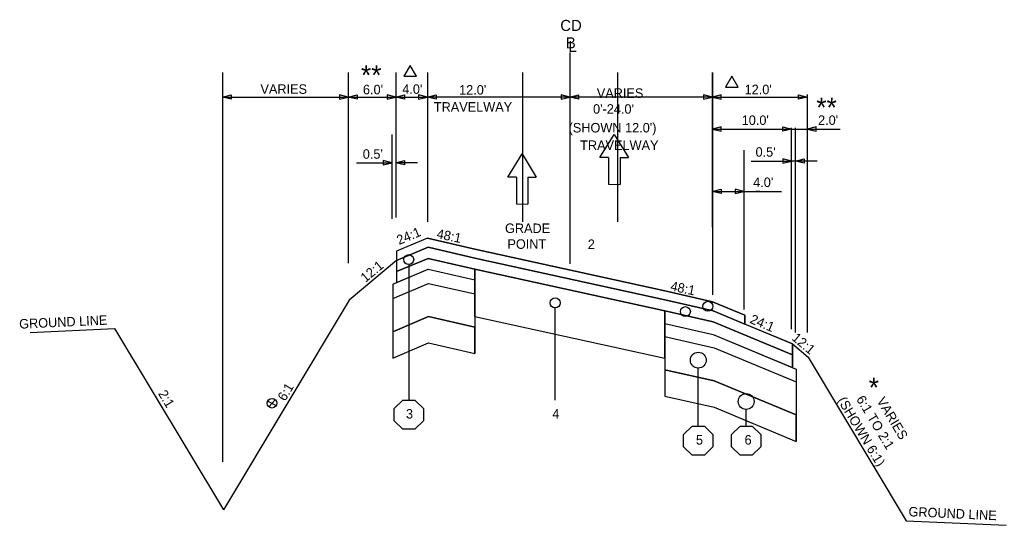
# Model space of a CAD drawing. Extents: x 5017 to 5774, y 4942 to 5266.
# Drawn here: x 5649.7 to 5774.4, y 4995.3 to 5059.2 of the extents above; entities that cross this region are included whole.
import ezdxf

# ---------------------------------------------------------------- set-up
doc = ezdxf.new("R2010")
doc.units = 0
for name, color, linetype in [('Level 20', 7, 'Continuous'), ('Level 25', 7, 'Continuous'), ('RD_QTY_Intermediate', 7, 'Continuous'), ('RD_QTY_Surf_Course', 7, 'Continuous'), ('RD_SHT_Typical', 7, 'Continuous'), ('RD_TX_TypSect', 7, 'Continuous'), ('RD_XS_ExGround', 7, 'Continuous'), ('RD_XS_ExPaveRet', 7, 'Continuous'), ('typical_on', 7, 'Continuous')]:
    doc.layers.add(name, color=color, linetype=linetype)

msp = doc.modelspace()

# ---------------------------------------------------------------- linework, layer by layer
at = {"layer": 'Level 20'}
for p, q in [((5723.05, 5041.76), (5724.87, 5044.67)), ((5724.87, 5044.67), (5726.65, 5041.75)), ((5711.4, 5039.28), (5713.23, 5042.2)), ((5713.23, 5042.2), (5715.01, 5039.27)), ((5724.14, 5041.76), (5723.05, 5041.76)), ((5724.14, 5041.76), (5724.14, 5038.36)), ((5725.6, 5041.75), (5726.65, 5041.75)), ((5725.6, 5041.75), (5725.6, 5038.35)), ((5712.5, 5039.28), (5711.4, 5039.28)), ((5712.5, 5039.28), (5712.5, 5035.88)), ((5713.95, 5039.27), (5715.01, 5039.27)), ((5713.95, 5039.27), (5713.95, 5035.87)), ((5724.14, 5038.36), (5725.6, 5038.35)), ((5712.5, 5035.88), (5713.95, 5035.87))]:
    msp.add_line(p, q, dxfattribs=at)
at = {"layer": 'RD_QTY_Intermediate'}
for p, q in [((5701.37, 5029), (5697.37, 5027.34)), ((5707.26, 5027.65), (5701.37, 5029)), ((5697.37, 5025.96), (5701.34, 5027.64)), ((5701.34, 5027.64), (5707.26, 5026.28)), ((5707.26, 5026.28), (5707.26, 5027.65)), ((5697.37, 5027.34), (5697.37, 5025.96)), ((5737.37, 5020.97), (5731.26, 5022.37)), ((5731.26, 5022.37), (5731.26, 5020.78)), ((5731.26, 5020.78), (5737.37, 5019.37)), ((5747.37, 5016.8), (5737.37, 5020.97)), ((5737.37, 5019.37), (5747.37, 5015.21)), ((5747.37, 5015.21), (5747.37, 5016.8))]:
    msp.add_line(p, q, dxfattribs=at)
at = {"layer": 'RD_QTY_Surf_Course'}
for p, q in [((5701.26, 5031.56), (5697.37, 5029.93)), ((5707.26, 5030.18), (5701.26, 5031.56)), ((5697.37, 5028.73), (5701.37, 5030.4)), ((5701.37, 5030.4), (5697.37, 5028.73)), ((5701.37, 5030.4), (5707.26, 5029.05)), ((5707.26, 5029.05), (5701.37, 5030.4)), ((5731.26, 5024.9), (5707.26, 5030.18)), ((5697.37, 5029.93), (5697.37, 5028.73)), ((5697.37, 5027.34), (5701.37, 5029)), ((5701.37, 5029), (5707.26, 5027.65)), ((5707.26, 5029.05), (5731.26, 5023.77)), ((5731.26, 5023.77), (5707.26, 5029.05)), ((5697.37, 5028.73), (5697.37, 5027.34)), ((5707.26, 5027.65), (5731.26, 5022.37)), ((5737.26, 5023.52), (5731.26, 5024.9)), ((5731.26, 5023.77), (5737.37, 5022.37)), ((5737.37, 5022.37), (5731.26, 5023.77)), ((5741.37, 5021.81), (5737.26, 5023.52)), ((5701.4, 5021.65), (5696.88, 5019.73)), ((5707.26, 5020.33), (5701.4, 5021.65)), ((5731.26, 5022.37), (5737.37, 5020.97)), ((5737.37, 5022.37), (5741.37, 5020.7)), ((5741.37, 5020.7), (5737.37, 5022.37)), ((5741.37, 5020.7), (5741.37, 5021.81)), ((5707.26, 5017), (5707.26, 5020.33)), ((5737.37, 5020.97), (5747.37, 5016.8)), ((5747.37, 5018.2), (5741.37, 5020.7)), ((5696.88, 5019.73), (5696.87, 5016.4)), ((5696.87, 5016.4), (5701.38, 5018.32)), ((5701.38, 5018.32), (5707.26, 5017)), ((5747.37, 5016.8), (5747.37, 5018.2)), ((5737.48, 5013.54), (5731.26, 5014.94)), ((5731.26, 5014.94), (5731.26, 5011.61)), ((5747.84, 5009.22), (5737.48, 5013.54)), ((5731.26, 5011.61), (5737.48, 5010.21)), ((5737.48, 5010.21), (5747.84, 5005.89)), ((5747.84, 5005.89), (5747.84, 5009.22))]:
    msp.add_line(p, q, dxfattribs=at)
at = {"layer": 'RD_SHT_Typical'}
for p, q in [((5701.26, 5031.56), (5697.37, 5029.93)), ((5701.26, 5031.56), (5707.26, 5030.18)), ((5701.37, 5030.4), (5697.37, 5028.73)), ((5701.37, 5030.4), (5707.26, 5029.05)), ((5707.26, 5030.18), (5731.26, 5024.9)), ((5697.37, 5029.93), (5697.37, 5025.95)), ((5701.37, 5029), (5697.37, 5027.34)), ((5701.37, 5029), (5707.26, 5027.65)), ((5707.26, 5029.05), (5731.26, 5023.77)), ((5697.37, 5028.73), (5691.37, 5023.73)), ((5696.87, 5025.75), (5701.34, 5027.64)), ((5701.34, 5027.64), (5707.26, 5026.28)), ((5707.26, 5027.65), (5731.26, 5022.37)), ((5707.26, 5021.67), (5707.26, 5027.65)), ((5707.26, 5027.65), (5707.26, 5026.28)), ((5696.87, 5023.92), (5701.38, 5025.83)), ((5696.87, 5025.75), (5696.87, 5023.92)), ((5707.26, 5026.28), (5707.26, 5024.52)), ((5696.87, 5023.92), (5696.87, 5019.73)), ((5707.26, 5024.52), (5707.26, 5020.33)), ((5731.26, 5024.9), (5737.26, 5023.52)), ((5691.37, 5023.73), (5675.47, 4997.23)), ((5731.26, 5023.77), (5737.37, 5022.37)), ((5737.26, 5023.52), (5741.37, 5021.81)), ((5696.88, 5019.73), (5701.4, 5021.65)), ((5707.26, 5021.67), (5731.26, 5016.39)), ((5731.26, 5022.37), (5737.37, 5020.97)), ((5731.26, 5016.39), (5731.26, 5022.37)), ((5731.26, 5022.37), (5731.26, 5020.78)), ((5737.37, 5022.37), (5747.37, 5018.2)), ((5741.37, 5021.81), (5741.37, 5020.7)), ((5661.73, 5020.13), (5675.47, 4997.23)), ((5707.26, 5020.33), (5707.26, 5017)), ((5731.26, 5020.78), (5737.37, 5019.37)), ((5731.26, 5020.78), (5731.26, 5019.12)), ((5737.37, 5020.97), (5747.37, 5016.8)), ((5696.88, 5019.73), (5696.88, 5016.41)), ((5731.26, 5019.12), (5731.26, 5014.94)), ((5737.37, 5019.37), (5747.87, 5015)), ((5696.87, 5016.4), (5701.38, 5018.32)), ((5737.51, 5017.72), (5747.87, 5013.4)), ((5747.37, 5018.2), (5747.37, 5015.21)), ((5747.37, 5018.2), (5749.37, 5016.53)), ((5749.37, 5016.53), (5761.77, 4995.87)), ((5731.26, 5014.94), (5731.26, 5011.61)), ((5747.87, 5015), (5747.87, 5013.4)), ((5737.48, 5013.54), (5747.84, 5009.22)), ((5747.87, 5013.4), (5747.87, 5009.21)), ((5737.48, 5010.21), (5747.84, 5005.89)), ((5747.84, 5009.22), (5747.84, 5005.89))]:
    msp.add_line(p, q, dxfattribs=at)
for points in [[(5701.38, 5025.83), (5707.26, 5024.52)], [(5701.4, 5021.65), (5707.26, 5020.33)], [(5731.26, 5019.12), (5737.51, 5017.72)], [(5701.38, 5018.32), (5707.26, 5017)], [(5731.26, 5014.94), (5737.48, 5013.54)], [(5731.26, 5011.61), (5737.48, 5010.21)]]:
    msp.add_lwpolyline(points, dxfattribs=at)
at = {"layer": 'RD_TX_TypSect'}
for p, q in [((5719.26, 5055.01), (5719.26, 5028.3)), ((5675.36, 5052.47), (5675.36, 5003.3)), ((5691.26, 5052.47), (5691.26, 5028.41)), ((5697.26, 5052.47), (5697.26, 5034.18)), ((5701.26, 5052.47), (5701.26, 5033.61)), ((5713.26, 5052.47), (5713.26, 5033.61)), ((5725.26, 5052.47), (5725.26, 5033.61)), ((5737.26, 5052.47), (5737.26, 5024.4)), ((5737.26, 5032.93), (5737.26, 5052.47)), ((5675.36, 5049.37), (5691.26, 5049.37)), ((5691.26, 5049.37), (5697.26, 5049.37)), ((5697.26, 5049.37), (5701.26, 5049.37)), ((5719.26, 5049.37), (5701.26, 5049.37)), ((5737.26, 5049.37), (5719.26, 5049.37)), ((5737.26, 5049.37), (5749.25, 5049.37)), ((5749.25, 5049.71), (5749.25, 5042.11)), ((5737.26, 5045.33), (5747.25, 5045.33)), ((5747.25, 5045.33), (5749.25, 5045.33)), ((5747.26, 5020.05), (5747.26, 5045.5)), ((5747.76, 5019.63), (5747.76, 5045.5)), ((5749.25, 5045.33), (5753.4, 5045.33)), ((5696.76, 5044.65), (5696.76, 5033.98)), ((5741.26, 5042.68), (5741.26, 5022.55)), ((5749.26, 5042.86), (5749.26, 5019.65)), ((5742.16, 5041.29), (5747.25, 5041.29)), ((5750.52, 5041.29), (5747.26, 5041.29)), ((5692.29, 5041.09), (5696.76, 5041.09)), ((5700.02, 5041.09), (5697.26, 5041.09)), ((5737.26, 5037.47), (5746.02, 5037.47)), ((5743.25, 5037.47), (5742.76, 5037.47)), ((5698.89, 5028.22), (5698.89, 5011.1)), ((5717.4, 5011.1), (5717.4, 5022.76)), ((5735.48, 5007.82), (5735.48, 5015.15)), ((5681.08, 5010.97), (5682.15, 5010.42)), ((5681.2, 5010.27), (5682.03, 5011.12)), ((5741.54, 5007.82), (5741.54, 5009.93))]:
    msp.add_line(p, q, dxfattribs=at)
for points in [[(5699.08, 5053.39), (5698.28, 5052.01), (5699.88, 5052.01)], [(5739.72, 5052.02), (5738.92, 5050.63), (5740.52, 5050.63)], [(5676.46, 5049.65), (5676.46, 5049.1), (5675.36, 5049.37)], [(5690.15, 5049.65), (5690.15, 5049.1), (5691.26, 5049.37)], [(5692.36, 5049.65), (5692.36, 5049.1), (5691.26, 5049.37)], [(5696.15, 5049.65), (5696.15, 5049.1), (5697.26, 5049.37)], [(5698.36, 5049.65), (5698.36, 5049.1), (5697.26, 5049.37)], [(5700.15, 5049.65), (5700.15, 5049.1), (5701.26, 5049.37)], [(5702.36, 5049.65), (5702.36, 5049.1), (5701.26, 5049.37)], [(5718.15, 5049.65), (5718.15, 5049.1), (5719.26, 5049.37)], [(5720.36, 5049.65), (5720.36, 5049.1), (5719.26, 5049.37)], [(5736.16, 5049.65), (5736.16, 5049.1), (5737.26, 5049.37)], [(5738.36, 5049.1), (5738.36, 5049.65), (5737.26, 5049.37)], [(5748.15, 5049.1), (5748.15, 5049.65), (5749.25, 5049.37)], [(5738.36, 5045.06), (5738.36, 5045.61), (5737.26, 5045.33)], [(5746.15, 5045.06), (5746.15, 5045.61), (5747.25, 5045.33)], [(5750.36, 5045.06), (5750.36, 5045.61), (5749.25, 5045.33)], [(5695.65, 5041.37), (5695.65, 5040.82), (5696.76, 5041.09)], [(5698.36, 5041.37), (5698.36, 5040.82), (5697.26, 5041.09)], [(5746.15, 5041.57), (5746.15, 5041.02), (5747.25, 5041.29)], [(5748.86, 5041.57), (5748.86, 5041.02), (5747.75, 5041.29)], [(5738.36, 5037.74), (5738.36, 5037.19), (5737.25, 5037.47)], [(5740.15, 5037.74), (5740.15, 5037.19), (5741.26, 5037.47)]]:
    msp.add_lwpolyline(points, close=True, dxfattribs=at)
for centre, radius in [((5698.89, 5028.85), 0.63), ((5717.4, 5023.38), 0.63), ((5733.85, 5022.28), 0.63), ((5736.7, 5022.95), 0.63), ((5735.48, 5016.15), 1), ((5741.54, 5010.93), 1), ((5681.62, 5010.7), 0.6)]:
    msp.add_circle(centre, radius, dxfattribs=at)
at = {"layer": 'RD_XS_ExGround'}
for p, q in [((5651.08, 5019.65), (5661.73, 5020.13)), ((5761.77, 4995.87), (5774.4, 4995.29))]:
    msp.add_line(p, q, dxfattribs=at)
at = {"layer": 'RD_XS_ExPaveRet'}
for p, q in [((5731.26, 5022.37), (5707.26, 5027.65)), ((5707.26, 5027.65), (5707.26, 5026.28)), ((5707.26, 5021.67), (5731.26, 5016.39)), ((5731.26, 5020.78), (5731.26, 5022.37))]:
    msp.add_line(p, q, dxfattribs=at)
for points in [[(5707.26, 5026.28), (5707.26, 5024.52), (5707.26, 5021.67)], [(5731.26, 5016.39), (5731.26, 5019.12), (5731.26, 5020.78)]]:
    msp.add_lwpolyline(points, dxfattribs=at)
at = {"layer": 'typical_on'}
for points in [[(5700.76, 5010.02), (5700.76, 5008.49), (5699.68, 5007.41), (5698.15, 5007.41), (5697.07, 5008.49), (5697.07, 5010.02), (5698.15, 5011.11), (5699.68, 5011.11)], [(5737.33, 5006.74), (5737.33, 5005.21), (5736.25, 5004.13), (5734.72, 5004.13), (5733.63, 5005.21), (5733.63, 5006.74), (5734.72, 5007.82), (5736.25, 5007.82)], [(5743.39, 5006.74), (5743.39, 5005.21), (5742.31, 5004.13), (5740.78, 5004.13), (5739.7, 5005.21), (5739.7, 5006.74), (5740.78, 5007.82), (5742.31, 5007.82)]]:
    msp.add_lwpolyline(points, close=True, dxfattribs=at)

# ---------------------------------------------------------------- texts
at = {"layer": 'Level 25'}
for s, p in [('GRADE', (5711.06, 5032.21)), ('POINT', (5711.37, 5030.21))]:
    msp.add_text(s, height=1.2, dxfattribs=at).set_placement(p)
at = {"layer": 'RD_TX_TypSect'}
for s, height, p in [('CD', 1.4, (5718.05, 5057.73)), ('B', 1.4, (5718.75, 5055.53)), ('L', 1.4, (5719.09, 5055.08)), ('**', 2.5, (5692.86, 5050.91)), ('VARIES', 1.2, (5680.16, 5049.79)), ("6.0'", 1.2, (5693.11, 5049.73)), ("4.0'", 1.2, (5698.08, 5049.79)), ("12.0'", 1.2, (5705.26, 5049.69)), ('VARIES', 1.2, (5722.66, 5049.28)), ("12.0'", 1.2, (5741.34, 5049.74)), ('TRAVELWAY', 1.2, (5702.07, 5047.54)), ('**', 2.5, (5750.39, 5046.82)), ("0'-24.0'", 1.2, (5722.19, 5047.28)), ("10.0'", 1.2, (5740.97, 5045.86)), ("2.0'", 1.2, (5750.62, 5045.86)), ("(SHOWN 12.0')", 1.2, (5719.1, 5044.91)), ('TRAVELWAY', 1.2, (5720.56, 5042.7)), ("0.5'", 1.2, (5693.09, 5041.59)), ("0.5'", 1.2, (5742.72, 5041.85)), ("4.0'", 1.2, (5742.42, 5038.02)), ('2', 1.2, (5721.52, 5030.19)), ('*', 2.5, (5757.02, 5011.44)), ('3', 1.2, (5698.55, 5008.77)), ('4', 1.2, (5717.04, 5008.77)), ('5', 1.2, (5735.19, 5005.48)), ('6', 1.2, (5741.33, 5005.48))]:
    msp.add_text(s, height=height, dxfattribs=at).set_placement(p)
for s, rotation, p in [('24:1', 22.6199, (5697.67, 5030.69)), ('48:1', 348.2317, (5702.35, 5031.57)), ('12:1', 39.8056, (5693.43, 5025.9)), ('48:1', 348.2317, (5731.89, 5024.96)), ('GROUND LINE', 2.6095, (5649.7, 5020.12)), ('24:1', 337.3801, (5741.91, 5020.88)), ('12:1', 320.1944, (5747.21, 5018.79)), ('6:1', 59.0362, (5683.28, 5010.88)), ('2:1', 300.9638, (5667.19, 5011.92)), ('(SHOWN 6:1)', 300.9638, (5753.04, 5011.07)), ('6:1 TO 2:1', 300.9638, (5755.4, 5011.23)), ('VARIES', 300.9638, (5757.98, 5011.02)), ('GROUND LINE', 357.3905, (5762.03, 4996.43))]:
    msp.add_text(s, height=1.2, rotation=rotation, dxfattribs=at).set_placement(p)

doc.saveas('drawing.dxf')
